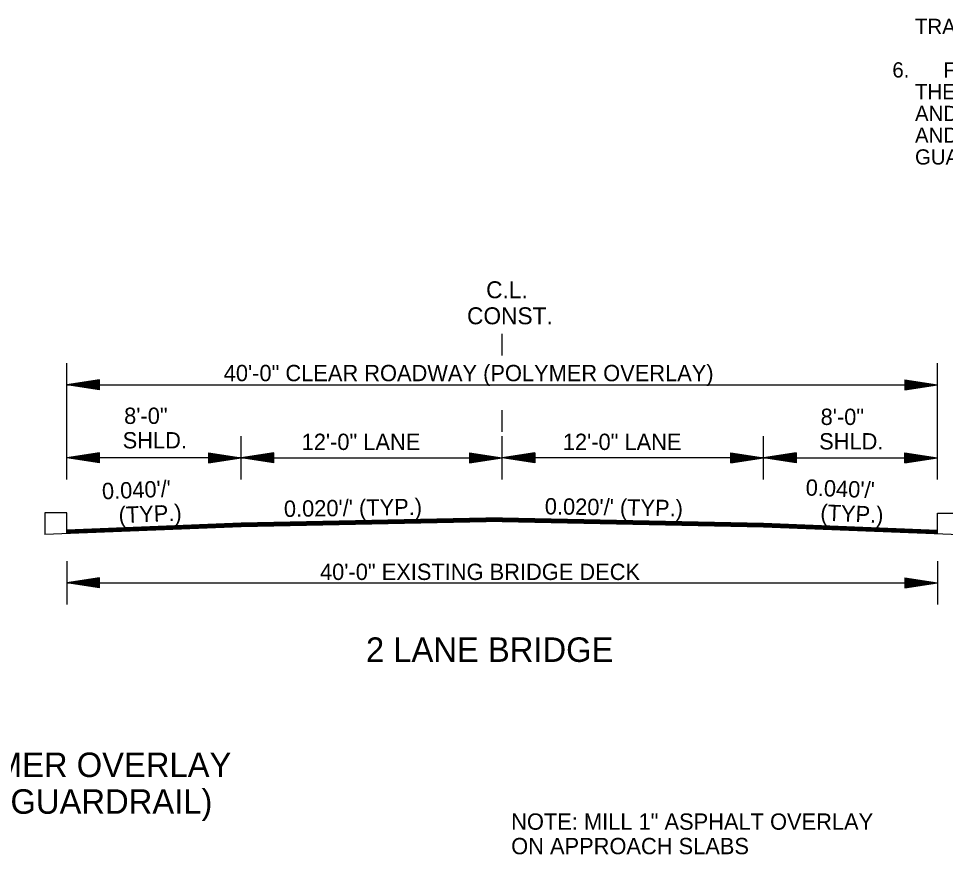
# Model space of a CAD drawing. Extents: x 545241 to 1930787, y -1971772 to 596640.
# Drawn here: x 547405.9 to 547831.8, y -1958708.4 to -1958324.3 of the extents above; entities that cross this region are included whole.
import ezdxf

# ---------------------------------------------------------------- set-up
doc = ezdxf.new("R2010")
doc.units = 0
for name, color, linetype in [('R_Border', 7, 'Continuous'), ('R_Border Notes', 7, 'Continuous'), ('R_Draft', 7, 'Continuous')]:
    doc.layers.add(name, color=color, linetype=linetype)

msp = doc.modelspace()

# ---------------------------------------------------------------- linework, layer by layer
at = {"layer": 'R_Border'}
for p, q in [((547628.13, -1958479.22), (547628.13, -1958469.22)), ((547428.13, -1958551.44), (547417.97, -1958551.44)), ((547417.97, -1958551.44), (547417.97, -1958561.45)), ((547428.13, -1958561.05), (547428.13, -1958551.44)), ((547828.13, -1958551.64), (547838.3, -1958551.64)), ((547828.13, -1958561.05), (547828.13, -1958551.64))]:
    msp.add_line(p, q, dxfattribs=at)
at = {"layer": 'R_Draft'}
for p, q in [((547428.13, -1958536.17), (547428.13, -1958482.63)), ((547828.13, -1958536.17), (547828.13, -1958482.63)), ((547443.13, -1958490.38), (547428.13, -1958492.63)), ((547428.13, -1958492.63), (547828.13, -1958492.63)), ((547443.13, -1958494.88), (547428.13, -1958492.63)), ((547443.13, -1958490.76), (547430.64, -1958492.63)), ((547443.13, -1958494.51), (547430.64, -1958492.63)), ((547443.13, -1958491.14), (547433.22, -1958492.63)), ((547443.13, -1958494.13), (547433.22, -1958492.63)), ((547443.13, -1958491.52), (547435.72, -1958492.63)), ((547443.13, -1958493.75), (547435.72, -1958492.63)), ((547443.13, -1958491.9), (547438.26, -1958492.63)), ((547443.13, -1958493.36), (547438.26, -1958492.63)), ((547443.13, -1958492.28), (547440.76, -1958492.63)), ((547443.13, -1958492.99), (547440.76, -1958492.63)), ((547443.13, -1958494.88), (547443.13, -1958490.38)), ((547813.13, -1958490.38), (547828.13, -1958492.63)), ((547813.13, -1958490.38), (547813.13, -1958494.88)), ((547813.13, -1958490.76), (547825.63, -1958492.63)), ((547813.13, -1958491.14), (547823.05, -1958492.63)), ((547813.13, -1958491.52), (547820.55, -1958492.63)), ((547813.13, -1958491.91), (547818.01, -1958492.63)), ((547813.13, -1958492.28), (547815.5, -1958492.63)), ((547813.13, -1958494.88), (547828.13, -1958492.63)), ((547813.13, -1958493.37), (547818.01, -1958492.63)), ((547813.13, -1958494.13), (547823.05, -1958492.63)), ((547813.13, -1958494.51), (547825.63, -1958492.63)), ((547813.13, -1958493.75), (547820.55, -1958492.63)), ((547813.13, -1958492.99), (547815.5, -1958492.63)), ((547628.13, -1958514.16), (547628.13, -1958504.29)), ((547508.13, -1958536.17), (547508.13, -1958516.28)), ((547628.13, -1958536.17), (547628.13, -1958516.28)), ((547748.13, -1958536.17), (547748.13, -1958516.28)), ((547443.13, -1958523.92), (547428.13, -1958526.17)), ((547443.13, -1958528.42), (547443.13, -1958523.92)), ((547493.13, -1958523.92), (547508.13, -1958526.17)), ((547493.13, -1958523.92), (547493.13, -1958528.42)), ((547523.13, -1958523.92), (547508.13, -1958526.17)), ((547523.13, -1958528.42), (547523.13, -1958523.92)), ((547613.13, -1958523.92), (547628.13, -1958526.17)), ((547613.13, -1958523.92), (547613.13, -1958528.42)), ((547643.13, -1958523.92), (547628.13, -1958526.17)), ((547643.13, -1958523.92), (547643.13, -1958528.42)), ((547733.13, -1958523.92), (547748.13, -1958526.17)), ((547733.13, -1958528.42), (547733.13, -1958523.92)), ((547763.13, -1958523.92), (547748.13, -1958526.17)), ((547763.13, -1958523.92), (547763.13, -1958528.42)), ((547813.13, -1958523.92), (547828.13, -1958526.17)), ((547813.13, -1958528.42), (547813.13, -1958523.92)), ((547508.13, -1958526.17), (547428.13, -1958526.17)), ((547443.13, -1958528.42), (547428.13, -1958526.17)), ((547443.13, -1958524.3), (547430.64, -1958526.17)), ((547443.13, -1958528.05), (547430.64, -1958526.17)), ((547443.13, -1958524.68), (547433.22, -1958526.17)), ((547443.13, -1958527.66), (547433.22, -1958526.17)), ((547443.13, -1958525.05), (547435.72, -1958526.17)), ((547443.13, -1958527.29), (547435.72, -1958526.17)), ((547443.13, -1958525.44), (547438.26, -1958526.17)), ((547443.13, -1958526.9), (547438.26, -1958526.17)), ((547443.13, -1958525.82), (547440.76, -1958526.17)), ((547443.13, -1958526.52), (547440.76, -1958526.17)), ((547493.13, -1958524.3), (547505.63, -1958526.17)), ((547493.13, -1958524.68), (547503.05, -1958526.17)), ((547493.13, -1958525.05), (547500.55, -1958526.17)), ((547493.13, -1958525.44), (547498.01, -1958526.17)), ((547493.13, -1958525.82), (547495.5, -1958526.17)), ((547493.13, -1958528.42), (547508.13, -1958526.17)), ((547493.13, -1958526.91), (547498.01, -1958526.17)), ((547493.13, -1958527.66), (547503.05, -1958526.17)), ((547493.13, -1958528.05), (547505.63, -1958526.17)), ((547493.13, -1958527.29), (547500.55, -1958526.17)), ((547493.13, -1958526.52), (547495.5, -1958526.17)), ((547523.13, -1958528.42), (547508.13, -1958526.17)), ((547508.13, -1958526.17), (547628.13, -1958526.17)), ((547523.13, -1958524.3), (547510.64, -1958526.17)), ((547523.13, -1958528.05), (547510.64, -1958526.17)), ((547523.13, -1958524.68), (547513.22, -1958526.17)), ((547523.13, -1958527.66), (547513.22, -1958526.17)), ((547523.13, -1958525.05), (547515.72, -1958526.17)), ((547523.13, -1958527.29), (547515.72, -1958526.17)), ((547523.13, -1958525.44), (547518.26, -1958526.17)), ((547523.13, -1958526.9), (547518.26, -1958526.17)), ((547523.13, -1958525.82), (547520.76, -1958526.17)), ((547523.13, -1958526.52), (547520.76, -1958526.17)), ((547613.13, -1958524.3), (547625.63, -1958526.17)), ((547613.13, -1958524.68), (547623.05, -1958526.17)), ((547613.13, -1958525.05), (547620.55, -1958526.17)), ((547613.13, -1958525.44), (547618.01, -1958526.17)), ((547613.13, -1958525.82), (547615.5, -1958526.17)), ((547613.13, -1958528.42), (547628.13, -1958526.17)), ((547613.13, -1958526.91), (547618.01, -1958526.17)), ((547613.13, -1958527.66), (547623.05, -1958526.17)), ((547613.13, -1958528.05), (547625.63, -1958526.17)), ((547613.13, -1958527.29), (547620.55, -1958526.17)), ((547613.13, -1958526.52), (547615.5, -1958526.17)), ((547748.13, -1958526.17), (547628.13, -1958526.17)), ((547643.13, -1958528.42), (547628.13, -1958526.17)), ((547643.13, -1958524.3), (547630.64, -1958526.17)), ((547643.13, -1958528.05), (547630.64, -1958526.17)), ((547643.13, -1958524.68), (547633.22, -1958526.17)), ((547643.13, -1958527.66), (547633.22, -1958526.17)), ((547643.13, -1958525.05), (547635.72, -1958526.17)), ((547643.13, -1958527.29), (547635.72, -1958526.17)), ((547643.13, -1958525.44), (547638.26, -1958526.17)), ((547643.13, -1958526.91), (547638.26, -1958526.17)), ((547643.13, -1958525.82), (547640.76, -1958526.17)), ((547643.13, -1958526.52), (547640.76, -1958526.17)), ((547733.13, -1958524.3), (547745.63, -1958526.17)), ((547733.13, -1958524.68), (547743.05, -1958526.17)), ((547733.13, -1958525.05), (547740.55, -1958526.17)), ((547733.13, -1958525.44), (547738.01, -1958526.17)), ((547733.13, -1958525.82), (547735.5, -1958526.17)), ((547733.13, -1958528.42), (547748.13, -1958526.17)), ((547733.13, -1958526.9), (547738.01, -1958526.17)), ((547733.13, -1958527.66), (547743.05, -1958526.17)), ((547733.13, -1958528.05), (547745.63, -1958526.17)), ((547733.13, -1958527.29), (547740.55, -1958526.17)), ((547733.13, -1958526.52), (547735.5, -1958526.17)), ((547763.13, -1958528.42), (547748.13, -1958526.17)), ((547748.13, -1958526.17), (547828.13, -1958526.17)), ((547763.13, -1958524.3), (547750.64, -1958526.17)), ((547763.13, -1958528.05), (547750.64, -1958526.17)), ((547763.13, -1958524.68), (547753.22, -1958526.17)), ((547763.13, -1958527.66), (547753.22, -1958526.17)), ((547763.13, -1958525.05), (547755.72, -1958526.17)), ((547763.13, -1958527.29), (547755.72, -1958526.17)), ((547763.13, -1958525.44), (547758.26, -1958526.17)), ((547763.13, -1958526.91), (547758.26, -1958526.17)), ((547763.13, -1958525.82), (547760.76, -1958526.17)), ((547763.13, -1958526.52), (547760.76, -1958526.17)), ((547813.13, -1958524.3), (547825.63, -1958526.17)), ((547813.13, -1958524.68), (547823.05, -1958526.17)), ((547813.13, -1958525.05), (547820.55, -1958526.17)), ((547813.13, -1958525.44), (547818.01, -1958526.17)), ((547813.13, -1958525.82), (547815.5, -1958526.17)), ((547813.13, -1958528.42), (547828.13, -1958526.17)), ((547813.13, -1958526.9), (547818.01, -1958526.17)), ((547813.13, -1958527.66), (547823.05, -1958526.17)), ((547813.13, -1958528.05), (547825.63, -1958526.17)), ((547813.13, -1958527.29), (547820.55, -1958526.17)), ((547813.13, -1958526.52), (547815.5, -1958526.17)), ((547628.13, -1958553.78), (547508.13, -1958556.18)), ((547628.13, -1958553.78), (547748.13, -1958556.18)), ((547508.13, -1958557.85), (547417.97, -1958561.45)), ((547508.13, -1958556.18), (547428.13, -1958559.38)), ((547508.13, -1958556.48), (547428.13, -1958559.68)), ((547508.13, -1958556.78), (547428.13, -1958559.98)), ((547508.13, -1958557.08), (547428.13, -1958560.28)), ((547508.13, -1958557.38), (547428.13, -1958560.58)), ((547508.13, -1958557.68), (547428.13, -1958560.88)), ((547628.14, -1958554.08), (547508.13, -1958556.48)), ((547628.15, -1958554.38), (547508.13, -1958556.78)), ((547628.15, -1958554.68), (547508.13, -1958557.08)), ((547628.16, -1958554.98), (547508.13, -1958557.38)), ((547628.16, -1958555.28), (547508.13, -1958557.68)), ((547628.17, -1958555.45), (547508.13, -1958557.85)), ((547628.1, -1958555.28), (547748.13, -1958557.68)), ((547628.1, -1958555.45), (547748.13, -1958557.85)), ((547628.11, -1958554.98), (547748.13, -1958557.38)), ((547628.12, -1958554.38), (547748.13, -1958556.78)), ((547628.12, -1958554.68), (547748.13, -1958557.08)), ((547628.13, -1958554.08), (547748.13, -1958556.48)), ((547748.13, -1958556.18), (547828.13, -1958559.38)), ((547748.13, -1958556.48), (547828.13, -1958559.68)), ((547748.13, -1958556.78), (547828.13, -1958559.98)), ((547748.13, -1958557.08), (547828.13, -1958560.28)), ((547748.13, -1958557.38), (547828.13, -1958560.58)), ((547748.13, -1958557.68), (547828.13, -1958560.88)), ((547748.13, -1958557.85), (547838.3, -1958561.45)), ((547428.13, -1958573.64), (547428.13, -1958593.64)), ((547828.13, -1958573.64), (547828.13, -1958593.64)), ((547443.13, -1958581.39), (547428.13, -1958583.64)), ((547428.13, -1958583.64), (547828.13, -1958583.64)), ((547443.13, -1958585.89), (547428.13, -1958583.64)), ((547443.13, -1958581.76), (547430.64, -1958583.64)), ((547443.13, -1958585.51), (547430.64, -1958583.64)), ((547443.13, -1958582.14), (547433.22, -1958583.64)), ((547443.13, -1958585.13), (547433.22, -1958583.64)), ((547443.13, -1958582.52), (547435.72, -1958583.64)), ((547443.13, -1958584.75), (547435.72, -1958583.64)), ((547443.13, -1958582.9), (547438.26, -1958583.64)), ((547443.13, -1958584.36), (547438.26, -1958583.64)), ((547443.13, -1958583.28), (547440.76, -1958583.64)), ((547443.13, -1958583.99), (547440.76, -1958583.64)), ((547443.13, -1958585.89), (547443.13, -1958581.39)), ((547813.13, -1958581.39), (547828.13, -1958583.64)), ((547813.13, -1958581.39), (547813.13, -1958585.89)), ((547813.13, -1958581.76), (547825.63, -1958583.64)), ((547813.13, -1958582.14), (547823.05, -1958583.64)), ((547813.13, -1958582.52), (547820.55, -1958583.64)), ((547813.13, -1958582.91), (547818.01, -1958583.64)), ((547813.13, -1958583.28), (547815.5, -1958583.64)), ((547813.13, -1958585.89), (547828.13, -1958583.64)), ((547813.13, -1958584.37), (547818.01, -1958583.64)), ((547813.13, -1958585.13), (547823.05, -1958583.64)), ((547813.13, -1958585.51), (547825.63, -1958583.64)), ((547813.13, -1958584.75), (547820.55, -1958583.64)), ((547813.13, -1958583.99), (547815.5, -1958583.64))]:
    msp.add_line(p, q, dxfattribs=at)

# ---------------------------------------------------------------- texts
at = {"layer": 'R_Border Notes'}
for s, p in [('    TRANSITIONS, GUARDRAIL WIDENING AND GUARDRAIL INSTALLATION INFORMATION.', (547807.36, -1958331.4)), ('6.      FOR HORIZONTAL AND VERTICAL CONTROLS AT GUARDRAIL LOCATIONS,', (547807.36, -1958351.4)), ('    THE GUARDRAIL WIDENING SLOPES AND GRADES SHALL MATCH THE SLOPES', (547807.36, -1958361.4)), ('    AND GRADES OF THE MAIN LANE SHOULDERS.  THE MAIN LANE TRANSITIONS', (547807.36, -1958371.4)), ('    AND ACHM EXTENSIONS SHALL BE PAVED PRIOR TO CONSTRUCTION OF THE', (547807.36, -1958381.4)), ('    GUARDRAIL WIDENING.', (547807.36, -1958391.4))]:
    msp.add_text(s, height=7, dxfattribs=at).set_placement(p)
at = {"layer": 'R_Draft'}
for s, height, p in [('C.L.', 7.8, (547620.72, -1958452.84)), ('CONST.', 7.8, (547611.94, -1958464.8)), ('40\'-0" CLEAR ROADWAY (POLYMER OVERLAY)', 7.5, (547500.16, -1958490.96)), ('8\'-0" ', 7.5, (547454.4, -1958510.6)), ('8\'-0" ', 7.5, (547774.4, -1958511.08)), ('SHLD.', 7.5, (547453.72, -1958521.85)), ('12\'-0" LANE', 7.5, (547535.95, -1958522.57)), ('12\'-0" LANE', 7.5, (547655.95, -1958522.57)), ('SHLD.', 7.5, (547773.72, -1958522.33)), ('40\'-0" EXISTING BRIDGE DECK', 7.5, (547544.39, -1958582.31)), ('2 LANE BRIDGE', 11.25, (547565.51, -1958619.95)), ('40 FT. CLEAR ROADWAY BRIDGE - POLYMER OVERLAY', 11.25, (547099.9, -1958672.87)), ('(ROADWAY TRANSITIONS AND NEW GUARDRAIL)', 11.25, (547134.71, -1958689.74)), ('NOTE: MILL 1" ASPHALT OVERLAY', 7.5, (547632.23, -1958697.09)), ('ON APPROACH SLABS', 7.5, (547632.23, -1958708.34))]:
    msp.add_text(s, height=height, dxfattribs=at).set_placement(p)
for s, rotation, p in [("0.040'/' ", 2.2906, (547444.36, -1958545.26)), ("0.040'/' ", 357.7094, (547767.42, -1958543.48)), ("0.020'/' (TYP.)", 0.8719, (547527.86, -1958553.36)), ("0.020'/' (TYP.)", 359.1281, (547647.63, -1958552.13)), ('(TYP.)', 2.2906, (547452.01, -1958556.21)), ('(TYP.)', 357.7094, (547774.17, -1958555.01))]:
    msp.add_text(s, height=7.5, rotation=rotation, dxfattribs=at).set_placement(p)

doc.saveas('drawing.dxf')
